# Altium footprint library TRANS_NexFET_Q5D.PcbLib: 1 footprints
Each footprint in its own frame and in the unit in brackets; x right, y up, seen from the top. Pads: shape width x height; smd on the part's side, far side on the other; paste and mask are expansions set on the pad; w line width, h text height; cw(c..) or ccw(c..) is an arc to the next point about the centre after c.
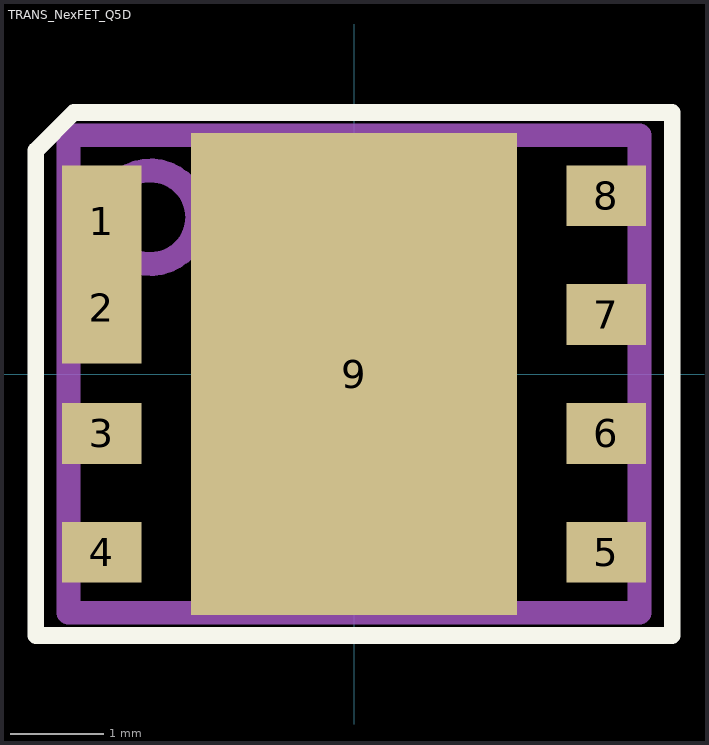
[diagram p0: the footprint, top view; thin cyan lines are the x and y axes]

## TRANS_NexFET_Q5D [mm] "TI recommended land pattern (nominal) M0188-01"
height 1.5
pads (9):
  rect 0.85x1.2 smd paste-0.1 mask+0.051: 1(-2.695,1.63) 2(-2.695,0.71)
  rect 0.85x0.65 smd paste-0.1 mask+0.051: 3(-2.695,-0.635) 4(-2.695,-1.905) 5(2.695,-1.905) 6(2.695,-0.635) 7(2.695,0.635) 8(2.695,1.905)
  rect 3.48x5.15 smd paste-2.2 mask+0.051: 9(0,0)
Top Overlay:
  lines w0.178: -3.4,-2.795 -3.4,0 -3.4,2.39 -2.995,2.795 0,2.795 3.4,2.795 3.4,0 3.4,-2.795 0,-2.795 -3.4,-2.795
Top Paste:
  region: 0.15,0.15 0.15,2.125 1.45,2.125 1.45,0.15
  region: -1.45,0.15 -1.45,2.125 -0.15,2.125 -0.15,0.15
  region: 0.15,-2.125 0.15,-0.15 1.45,-0.15 1.45,-2.125
  region: -1.45,-2.125 -1.45,-0.15 -0.15,-0.15 -0.15,-2.125
M5 Assembly Top:
  text ".Designator" at -1.529,-0.508 h1.02
M13 Component Bodies Top:
  circle w0.254: c-2.175,1.675 r0.5
  lines w0.254: -3.05,-2.55 3.05,-2.55 3.05,2.55 -3.05,2.55 -3.05,-2.55
3D body: height 1.51, standoff 1, extent -2.684,1.166 -1.666,2.184
3D body: height 1.5, standoff 0, extent -3.05,-2.549 3.049,2.549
